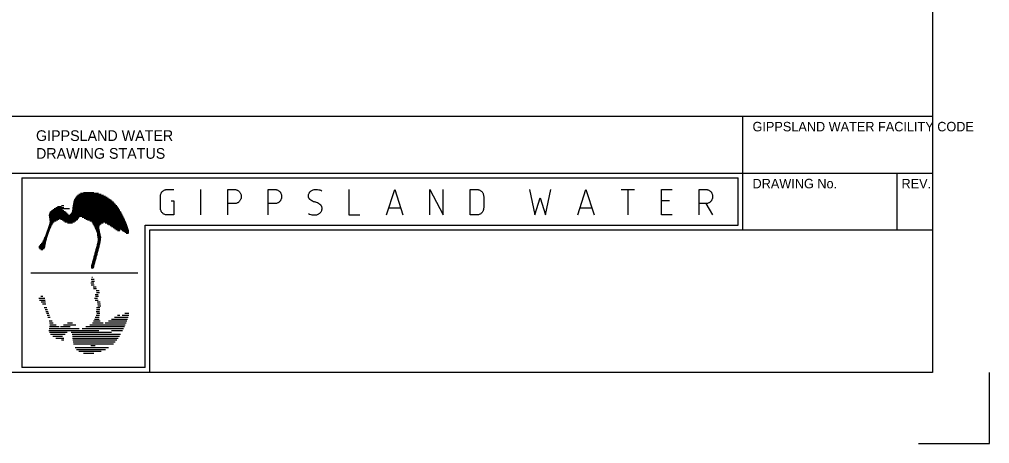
# Model space of a CAD drawing. Extents: x 0 to 841, y 0 to 594.
# Drawn here: x 636.5 to 841, y 0 to 89.4 of the extents above; entities that cross this region are included whole.
import ezdxf

# ---------------------------------------------------------------- set-up
doc = ezdxf.new("R2010")
doc.units = 0
doc.layers.add('A1BORDER', color=7, linetype='Continuous')

msp = doc.modelspace()

# ---------------------------------------------------------------- linework, layer by layer
at = {"layer": 'A1BORDER'}
for p, q in [((829, 581), (829, 15)), ((592.5, 69), (829, 69)), ((789, 45), (789, 69)), ((28, 57), (829, 57)), ((637, 56), (788, 56)), ((637, 56), (637, 16)), ((788, 46), (788, 56)), ((821.5, 45), (821.5, 57)), ((648.03, 51.32), (655.85, 51.32)), ((648.12, 51.52), (655.59, 51.52)), ((648.23, 51.72), (655.31, 51.72)), ((648.37, 51.92), (655, 51.92)), ((648.53, 52.12), (654.64, 52.12)), ((648.74, 52.32), (654.24, 52.32)), ((649.02, 52.52), (653.76, 52.52)), ((649.39, 52.72), (653.15, 52.72)), ((650.01, 52.92), (652.2, 52.92)), ((643.26, 49.12), (645.9, 49.12)), ((643.54, 49.32), (645.57, 49.32)), ((643.85, 49.52), (647.09, 49.52)), ((644.18, 49.72), (645.89, 49.72)), ((644.54, 49.92), (645.36, 49.92)), ((645.37, 50.12), (645.86, 50.12)), ((647.63, 49.12), (657.68, 49.12)), ((647.66, 49.32), (657.57, 49.32)), ((647.69, 49.52), (657.44, 49.52)), ((647.71, 49.72), (657.31, 49.72)), ((647.75, 49.92), (657.17, 49.92)), ((647.78, 50.12), (657.02, 50.12)), ((647.81, 50.32), (656.86, 50.32)), ((647.85, 50.52), (656.69, 50.52)), ((647.88, 50.72), (656.5, 50.72)), ((647.91, 50.92), (656.3, 50.92)), ((647.96, 51.12), (656.08, 51.12)), ((642.73, 48.12), (658.25, 48.12)), ((642.74, 47.92), (658.35, 47.92)), ((642.75, 48.32), (646.79, 48.32)), ((642.79, 47.72), (649.08, 47.72)), ((642.81, 48.52), (646.55, 48.52)), ((642.83, 47.52), (648.95, 47.52)), ((642.85, 47.31), (644.88, 47.31)), ((642.87, 47.12), (644.57, 47.12)), ((642.9, 48.72), (646.37, 48.72)), ((643.04, 48.92), (646.16, 48.92)), ((645.14, 47.31), (648.83, 47.31)), ((645.49, 47.12), (648.67, 47.12)), ((647.19, 48.32), (658.14, 48.32)), ((647.42, 48.52), (658.03, 48.52)), ((647.54, 48.72), (657.92, 48.72)), ((647.61, 48.92), (657.8, 48.92)), ((649.72, 47.72), (658.45, 47.72)), ((650.12, 47.52), (658.55, 47.52)), ((650.48, 47.31), (658.64, 47.31)), ((650.87, 47.12), (658.73, 47.12)), ((642.43, 45.12), (642.9, 45.12)), ((642.5, 45.32), (643, 45.32)), ((642.57, 45.52), (643.1, 45.52)), ((642.65, 45.72), (643.2, 45.72)), ((642.72, 45.92), (643.3, 45.92)), ((642.79, 46.12), (643.4, 46.12)), ((642.84, 46.32), (643.5, 46.32)), ((642.87, 46.52), (643.6, 46.52)), ((642.88, 46.92), (644.23, 46.92)), ((642.88, 46.72), (643.83, 46.72)), ((645.76, 46.92), (648.42, 46.92)), ((646.05, 46.72), (648.11, 46.72)), ((646.62, 46.52), (647.67, 46.52)), ((651.36, 46.92), (658.82, 46.92)), ((651.76, 46.72), (658.9, 46.72)), ((651.88, 46.52), (654.15, 46.52)), ((651.99, 46.32), (653.71, 46.32)), ((652.1, 46.12), (653.52, 46.12)), ((652.2, 45.92), (653.4, 45.92)), ((652.31, 45.72), (653.33, 45.72)), ((652.41, 45.52), (653.31, 45.52)), ((652.5, 45.32), (653.34, 45.32)), ((652.6, 45.12), (653.38, 45.12)), ((654.57, 46.52), (658.99, 46.52)), ((655, 46.32), (659.07, 46.32)), ((655.31, 46.12), (659.14, 46.12)), ((655.62, 45.92), (659.22, 45.92)), ((655.93, 45.72), (659.29, 45.72)), ((656.24, 45.52), (659.35, 45.52)), ((656.55, 45.32), (659.42, 45.32)), ((656.86, 45.12), (657.74, 45.12)), ((657.91, 45.12), (659.48, 45.12)), ((663, 46), (788, 46)), ((663, 16), (663, 46)), ((664, 45), (829, 45)), ((664, 15), (664, 45)), ((641.64, 43.12), (642.25, 43.12)), ((641.73, 43.32), (642.3, 43.32)), ((641.82, 43.51), (642.35, 43.51)), ((641.91, 43.72), (642.41, 43.72)), ((641.99, 43.92), (642.48, 43.92)), ((642.06, 44.12), (642.55, 44.12)), ((642.13, 44.32), (642.62, 44.32)), ((642.21, 44.52), (642.69, 44.52)), ((642.28, 44.72), (642.76, 44.72)), ((642.35, 44.92), (642.83, 44.92)), ((652.69, 44.92), (653.41, 44.92)), ((652.78, 44.72), (653.44, 44.72)), ((652.83, 44.52), (653.48, 44.52)), ((652.86, 44.32), (653.53, 44.32)), ((652.89, 44.12), (653.57, 44.12)), ((652.91, 43.92), (653.62, 43.92)), ((652.94, 43.72), (653.67, 43.72)), ((652.97, 43.51), (653.71, 43.51)), ((653, 43.32), (653.69, 43.32)), ((653.02, 43.12), (653.67, 43.12)), ((657.17, 44.92), (657.68, 44.92)), ((657.51, 44.72), (657.54, 44.72)), ((658.19, 44.92), (659.54, 44.92)), ((658.47, 44.72), (659.59, 44.72)), ((658.75, 44.52), (659.58, 44.52)), ((659.02, 44.32), (659.47, 44.32)), ((640.62, 41.32), (641.88, 41.32)), ((640.63, 41.52), (641.93, 41.52)), ((640.72, 41.12), (641.73, 41.12)), ((640.73, 41.72), (641.95, 41.72)), ((640.9, 41.92), (641.97, 41.92)), ((641.03, 40.92), (641.43, 40.92)), ((641.1, 42.12), (642, 42.12)), ((641.25, 42.31), (642.04, 42.31)), ((641.37, 42.52), (642.09, 42.52)), ((641.46, 42.72), (642.15, 42.72)), ((641.55, 42.92), (642.2, 42.92)), ((652.57, 40.92), (653.2, 40.92)), ((652.63, 41.12), (653.26, 41.12)), ((652.68, 41.32), (653.31, 41.32)), ((652.74, 41.52), (653.37, 41.52)), ((652.79, 41.72), (653.41, 41.72)), ((652.85, 41.92), (653.45, 41.92)), ((652.9, 42.12), (653.49, 42.12)), ((652.95, 42.31), (653.53, 42.31)), ((652.99, 42.52), (653.57, 42.52)), ((653.03, 42.72), (653.61, 42.72)), ((653.05, 42.92), (653.64, 42.92)), ((652.03, 38.92), (652.66, 38.92)), ((652.09, 39.12), (652.72, 39.12)), ((652.14, 39.32), (652.77, 39.32)), ((652.2, 39.52), (652.82, 39.52)), ((652.25, 39.72), (652.88, 39.72)), ((652.3, 39.92), (652.93, 39.92)), ((652.36, 40.12), (652.99, 40.12)), ((652.41, 40.32), (653.04, 40.32)), ((652.47, 40.52), (653.1, 40.52)), ((652.52, 40.72), (653.15, 40.72)), ((651.63, 37.32), (652.23, 37.32)), ((651.64, 37.12), (652.17, 37.12)), ((651.65, 37.52), (652.28, 37.52)), ((651.71, 37.72), (652.34, 37.72)), ((651.76, 37.92), (652.39, 37.92)), ((651.79, 36.92), (651.9, 36.92)), ((651.82, 38.12), (652.44, 38.12)), ((651.87, 38.32), (652.5, 38.32)), ((651.92, 38.52), (652.55, 38.52)), ((651.98, 38.72), (652.61, 38.72)), ((638.93, 35.98), (661.47, 35.98)), ((651.79, 35.04), (651.9, 35.04)), ((651.54, 33.84), (652.17, 33.84)), ((651.63, 34.64), (652.23, 34.64)), ((651.65, 33.44), (652.28, 33.44)), ((651.71, 34.24), (652.34, 34.24)), ((652.03, 33.04), (652.66, 33.04)), ((641.03, 31.04), (641.43, 31.04)), ((652.14, 32.64), (652.77, 32.64)), ((652.47, 31.44), (653.1, 31.44)), ((652.57, 31.04), (653.2, 31.04)), ((652.66, 32.24), (653.29, 32.24)), ((652.77, 31.84), (653.4, 31.84)), ((640.62, 30.64), (641.88, 30.64)), ((640.73, 30.24), (641.95, 30.24)), ((641.1, 29.84), (642, 29.84)), ((641.37, 29.44), (642.09, 29.44)), ((641.73, 28.64), (642.3, 28.64)), ((652.34, 30.64), (652.97, 30.64)), ((652.45, 30.24), (653.07, 30.24)), ((652.77, 28.64), (653.46, 28.64)), ((652.9, 29.84), (653.49, 29.84)), ((652.99, 29.44), (653.57, 29.44)), ((653.05, 29.04), (653.64, 29.04)), ((641.91, 28.24), (642.41, 28.24)), ((642.06, 27.84), (642.55, 27.84)), ((642.21, 27.44), (642.69, 27.44)), ((642.35, 27.04), (642.83, 27.04)), ((642.5, 26.64), (643, 26.64)), ((652.5, 26.64), (653.34, 26.64)), ((652.66, 27.84), (653.35, 27.84)), ((652.69, 27.04), (653.41, 27.04)), ((652.72, 28.24), (653.44, 28.24)), ((652.83, 27.44), (653.48, 27.44)), ((656.55, 26.64), (659.42, 26.64)), ((657.17, 27.04), (657.68, 27.04)), ((658.19, 27.04), (659.54, 27.04)), ((658.75, 27.44), (659.58, 27.44)), ((642.79, 25.84), (643.4, 25.84)), ((642.85, 24.65), (644.88, 24.65)), ((642.87, 25.44), (643.6, 25.44)), ((642.88, 25.04), (644.23, 25.04)), ((645.14, 24.65), (647.18, 24.65)), ((645.76, 25.04), (648.42, 25.04)), ((646.62, 25.44), (647.67, 25.44)), ((650.48, 24.65), (658.64, 24.65)), ((651.36, 25.04), (658.82, 25.04)), ((651.88, 25.44), (654.15, 25.44)), ((652.1, 25.84), (653.52, 25.84)), ((652.31, 26.24), (653.33, 26.24)), ((654.57, 25.44), (658.99, 25.44)), ((655.31, 25.84), (659.14, 25.84)), ((655.93, 26.24), (659.29, 26.24)), ((642.73, 23.84), (653.27, 23.84)), ((642.79, 24.24), (649.08, 24.24)), ((642.81, 23.44), (646.55, 23.44)), ((643.04, 23.04), (646.16, 23.04)), ((643.54, 22.64), (645.57, 22.64)), ((647.42, 23.44), (655.89, 23.44)), ((647.61, 23.04), (657.8, 23.04)), ((647.66, 22.64), (657.57, 22.64)), ((649.72, 24.24), (658.45, 24.24)), ((655.94, 23.84), (658.25, 23.84)), ((644.18, 22.24), (645.89, 22.24)), ((645.37, 21.84), (645.86, 21.84)), ((647.71, 22.24), (657.31, 22.24)), ((647.78, 21.84), (657.02, 21.84)), ((647.85, 21.44), (656.69, 21.44)), ((647.91, 21.04), (656.3, 21.04)), ((651.57, 20.64), (652.44, 20.64)), ((648.23, 20.24), (655.31, 20.24)), ((648.53, 19.84), (654.64, 19.84)), ((649.02, 19.44), (653.76, 19.44)), ((650.01, 19.04), (652.2, 19.04)), ((829, 15), (28, 15)), ((663, 16), (637, 16)), ((829, 15), (829, 15)), ((841, 0), (841, 15)), ((826, 0), (841, 0))]:
    msp.add_line(p, q, dxfattribs=at)
for points in [[(668.49, 51.15), (669.06, 51.15), (669.06, 48.16), (667.64, 48.16), (667.51, 48.16), (667.39, 48.18), (667.28, 48.21), (667.15, 48.25), (667.04, 48.3), (666.93, 48.36), (666.82, 48.43), (666.73, 48.51), (666.64, 48.6), (666.55, 48.7), (666.48, 48.8), (666.41, 48.91), (666.35, 49.02), (666.31, 49.14), (666.27, 49.27), (666.24, 49.39), (666.22, 49.52), (666.22, 49.66), (666.22, 52.05), (666.22, 52.18), (666.24, 52.31), (666.27, 52.43), (666.31, 52.56), (666.35, 52.67), (666.41, 52.79), (666.48, 52.9), (666.55, 53), (666.64, 53.1), (666.73, 53.19), (666.82, 53.27), (666.93, 53.34), (667.04, 53.4), (667.15, 53.45), (667.28, 53.49), (667.39, 53.52), (667.51, 53.54), (667.64, 53.54), (669.06, 53.54)], [(674.74, 48.16), (674.74, 53.54)], [(680.42, 48.16), (680.42, 53.54), (681.84, 53.54), (681.96, 53.54), (682.08, 53.52), (682.2, 53.49), (682.32, 53.45), (682.43, 53.4), (682.54, 53.34), (682.65, 53.27), (682.74, 53.19), (682.84, 53.1), (682.92, 53), (682.99, 52.9), (683.06, 52.79), (683.12, 52.67), (683.17, 52.56), (683.21, 52.43), (683.23, 52.31), (683.25, 52.18), (683.26, 52.05), (683.25, 51.91), (683.23, 51.78), (683.21, 51.66), (683.17, 51.53), (683.12, 51.42), (683.06, 51.3), (682.99, 51.19), (682.92, 51.09), (682.84, 50.99), (682.74, 50.9), (682.65, 50.82), (682.54, 50.75), (682.43, 50.69), (682.32, 50.64), (682.2, 50.6), (682.08, 50.57), (681.96, 50.55), (681.84, 50.55), (680.42, 50.55)], [(688.93, 48.16), (688.93, 53.54), (690.35, 53.54), (690.47, 53.54), (690.59, 53.52), (690.71, 53.49), (690.83, 53.45), (690.94, 53.4), (691.05, 53.34), (691.16, 53.27), (691.26, 53.19), (691.35, 53.1), (691.43, 53), (691.51, 52.9), (691.57, 52.79), (691.63, 52.67), (691.68, 52.56), (691.72, 52.43), (691.75, 52.31), (691.76, 52.18), (691.77, 52.05), (691.76, 51.91), (691.75, 51.78), (691.72, 51.66), (691.68, 51.53), (691.63, 51.42), (691.57, 51.3), (691.51, 51.19), (691.43, 51.09), (691.35, 50.99), (691.26, 50.9), (691.16, 50.82), (691.05, 50.75), (690.94, 50.69), (690.83, 50.64), (690.71, 50.6), (690.59, 50.57), (690.47, 50.55), (690.35, 50.55), (688.93, 50.55)], [(697.45, 48.46), (697.67, 48.36), (697.9, 48.27), (698.12, 48.21), (698.36, 48.17), (698.6, 48.16), (698.84, 48.16), (698.87, 48.16), (699.03, 48.18), (699.18, 48.21), (699.33, 48.26), (699.48, 48.32), (699.62, 48.4), (699.72, 48.46), (699.81, 48.53), (699.9, 48.61), (699.98, 48.69), (700.05, 48.78), (700.11, 48.88), (700.17, 48.99), (700.22, 49.09), (700.25, 49.21), (700.28, 49.32), (700.29, 49.36), (700.3, 49.44), (700.3, 49.52), (700.3, 49.61), (700.29, 49.69), (700.27, 49.77), (700.25, 49.86), (700.22, 49.93), (700.18, 50.01), (700.14, 50.09), (700.09, 50.15), (700.04, 50.21), (700.01, 50.25), (699.85, 50.39), (699.69, 50.51), (699.52, 50.61), (699.34, 50.7), (699.15, 50.78), (698.95, 50.83), (698.87, 50.85), (698.68, 50.9), (698.49, 50.96), (698.3, 51.04), (698.12, 51.14), (697.96, 51.26), (697.8, 51.39), (697.73, 51.45), (697.67, 51.51), (697.62, 51.57), (697.58, 51.64), (697.53, 51.71), (697.5, 51.79), (697.47, 51.87), (697.46, 51.95), (697.44, 52.04), (697.43, 52.12), (697.43, 52.21), (697.44, 52.29), (697.45, 52.35), (697.47, 52.46), (697.51, 52.58), (697.55, 52.69), (697.61, 52.79), (697.67, 52.89), (697.74, 52.99), (697.82, 53.07), (697.9, 53.15), (697.99, 53.23), (698.02, 53.24), (698.15, 53.33), (698.3, 53.4), (698.44, 53.45), (698.6, 53.5), (698.75, 53.52), (698.87, 53.54), (699.11, 53.55), (699.35, 53.53), (699.58, 53.49), (699.82, 53.43), (700.04, 53.35), (700.27, 53.25)], [(705.96, 53.54), (705.96, 48.16), (708.23, 48.16)], [(713.91, 48.16), (715.61, 53.54), (717.32, 48.16)], [(722.99, 48.16), (722.99, 53.54), (725.83, 48.16), (725.83, 53.54)], [(731.52, 48.16), (731.52, 53.54), (732.94, 53.54), (733.06, 53.54), (733.18, 53.52), (733.3, 53.49), (733.42, 53.45), (733.53, 53.4), (733.64, 53.34), (733.75, 53.27), (733.84, 53.19), (733.94, 53.1), (734.02, 53), (734.09, 52.9), (734.16, 52.79), (734.22, 52.67), (734.27, 52.56), (734.31, 52.43), (734.33, 52.31), (734.35, 52.18), (734.36, 52.05), (734.36, 49.66), (734.35, 49.52), (734.33, 49.39), (734.31, 49.27), (734.27, 49.14), (734.22, 49.02), (734.16, 48.91), (734.09, 48.8), (734.02, 48.7), (733.94, 48.6), (733.84, 48.51), (733.75, 48.43), (733.64, 48.36), (733.53, 48.3), (733.42, 48.25), (733.3, 48.21), (733.18, 48.18), (733.06, 48.16), (732.94, 48.16), (731.52, 48.16)], [(744.01, 53.54), (745.14, 48.16), (746.28, 51.75), (747.41, 48.16), (748.55, 53.54)], [(754.22, 48.16), (755.92, 53.54), (757.63, 48.16)], [(763.31, 53.54), (766.15, 53.54)], [(764.73, 53.54), (764.73, 48.16)], [(774.09, 48.16), (771.82, 48.16), (771.82, 53.54), (774.09, 53.54)], [(779.78, 48.16), (779.78, 53.54), (781.2, 53.54), (781.32, 53.54), (781.44, 53.52), (781.56, 53.49), (781.68, 53.45), (781.79, 53.4), (781.9, 53.34), (782.01, 53.27), (782.1, 53.19), (782.2, 53.1), (782.28, 53), (782.35, 52.9), (782.42, 52.79), (782.48, 52.67), (782.53, 52.56), (782.56, 52.43), (782.59, 52.31), (782.61, 52.18), (782.61, 52.05), (782.61, 51.91), (782.59, 51.78), (782.56, 51.66), (782.53, 51.53), (782.48, 51.42), (782.42, 51.3), (782.35, 51.19), (782.28, 51.09), (782.2, 50.99), (782.1, 50.9), (782.01, 50.82), (781.9, 50.75), (781.79, 50.69), (781.68, 50.64), (781.56, 50.6), (781.44, 50.57), (781.32, 50.55), (781.2, 50.55), (779.78, 50.55)], [(773.53, 51.15), (771.82, 51.15)], [(714.48, 49.66), (716.75, 49.66)], [(754.79, 49.66), (757.06, 49.66)], [(781.2, 50.55), (782.61, 48.16)]]:
    msp.add_lwpolyline(points, dxfattribs=at)

# ---------------------------------------------------------------- texts
for s, height, p in [('GIPPSLAND WATER FACILITY CODE', 2, (791.03, 65.77)), ('GIPPSLAND WATER', 2.25, (640, 63.75)), ('DRAWING STATUS', 2.25, (640, 60)), ('DRAWING No.', 2, (791.03, 53.77)), ('REV.', 2, (822.43, 53.77))]:
    msp.add_text(s, height=height, dxfattribs=at).set_placement(p)

doc.saveas('drawing.dxf')
